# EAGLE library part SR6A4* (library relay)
Safety Relay SR6 SCHRACK sensitive 6 pole 8 A Source: http://www.schrack.com/.. 6688.pdf
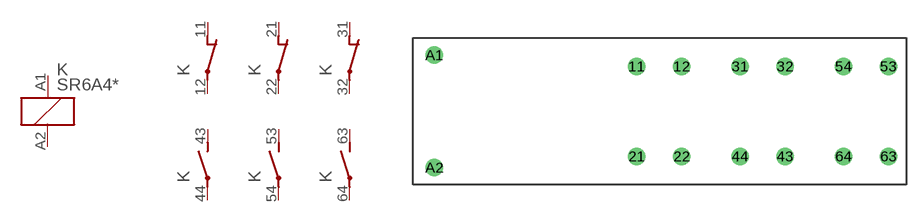
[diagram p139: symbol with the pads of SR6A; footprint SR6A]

Designator prefix K; gates 1=K 2=O 3=O 4=O 5=S 6=S 7=S

## SR6A4S05 (OC_FARNELL: unknown; OC_NEWARK: unknown), SR6A4S06 (OC_FARNELL: unknown; OC_NEWARK: unknown), SR6A4S09 (OC_FARNELL: unknown; OC_NEWARK: unknown), SR6A4S12 (OC_FARNELL: unknown; OC_NEWARK: unknown), SR6A4S15 (OC_FARNELL: unknown; OC_NEWARK: unknown), SR6A4S18 (OC_FARNELL: unknown; OC_NEWARK: unknown), SR6A4S21 (OC_FARNELL: unknown; OC_NEWARK: unknown), SR6A4S24 (OC_FARNELL: unknown; OC_NEWARK: unknown), SR6A4S36 (OC_FARNELL: unknown; OC_NEWARK: unknown), SR6A4S40 (OC_FARNELL: unknown; OC_NEWARK: unknown), SR6A4S48 (OC_FARNELL: unknown; OC_NEWARK: unknown)  [SR6A]
11  2:O  pas
12  2:P  pas
21  3:O  pas
22  3:P  pas
31  4:O  pas
32  4:P  pas
43  5:S  pas
44  5:P  pas
53  6:S  pas
54  6:P  pas
63  7:S  pas
64  7:P  pas
A1  1:1  pas
A2  1:2  pas

## Footprint SR6A (pad centres in mm)
Safety Relay SR6 SCHRACK sensitive 6 pole 8 A, Type A and B Source: http://www.schrack.com/.. 6688.pdf
drill 1.3 pad 1 round: 11 -0.3,4.7; 12 4.7,4.7; 21 -0.3,-5.3; 22 4.7,-5.3; 31 11.2,4.7; 32 16.2,4.7; 43 16.2,-5.3; 44 11.2,-5.3; 53 27.7,4.7; 54 22.7,4.7; 63 27.7,-5.3; 64 22.7,-5.3; A1 -22.8,5.95; A2 -22.8,-6.55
